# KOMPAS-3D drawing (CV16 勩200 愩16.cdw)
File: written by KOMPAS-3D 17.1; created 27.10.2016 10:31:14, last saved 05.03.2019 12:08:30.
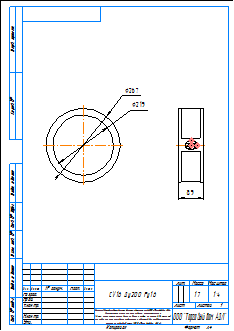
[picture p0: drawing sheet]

Sheet 1: A4, portrait

Title block, sheet 1: name: CV16 Ду200 Ру16; material: Сталь 20  ГОСТ 1050-88; mass: 17; sheets: 1; sheet format: A4; stored path: \\adlc.lan\data\АДЛ_ПКД\3D-модели\ADL production\Клапаны обратные ГРАНЛОК\CV16\KOMPAS 2D\CV16 Ду200 Ру16.cdw

Views: Вид 1, Проекционный вид 2
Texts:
  Klimkovich
  ADL
  Рама для чертежей
  Лит-Масса-Масштаб
  Материал-Предприятие
  Масштаб
  Изм.
  Лист
  № докум.
  Подп.
  Дата
  Лит.
  Разраб.
  Пров.
  Т.контр.
  Листов
  Внимание! Данный продукт является объектом авторского права ООО «Торговый Дом АДЛ».
  Запрещается изменение, копирование, распространение
  (в том числе путем копирования на другие сайты и ресурсы в Интернете)
  или любое иное использование информации и объектов без предварительного
  согласия правообладателя (ООО «Торговый Дом АДЛ»).
  Н.контр.
  Утв.
  ООО "Торговый дом АДЛ"
  Изменение
  Номер документа
  Подпись
  Обозначение документа
  Наименование изделия
  Масса изделия по ГОСТ 2.109-73
  Порядковый номер листа
  Общее количество листов в документе
  Характер работы, выполненной лицом, подписавшим документ
  Наименование или индекс предприятия, выпускающего документ
  Инв. № подл.
  Подп. и дата
  Взам. инв. №
  Инв. № дубл.
  Инвентарный номер подлинника по ГОСТ 2.501-68
  Подпись принявшего подлинник в отдел технической документации
  Инвентарный номер подлинника, взамен которого выпущен данный подлинник
  Инвентарный номер дубликата по ГОСТ 2.502-68
  Подпись принявшего дубликат в отдел технической документации
  Справ. №
  Перв. примен.
  Обозначение документа, взамен или на основании которого выпущен данный документ
  Обозначение документа, в котором впервые записан данный документ
  Подпись лица, копировавшего чертеж
  Обозначение формата листа
  !Рама для чертежа
Dimensions and other numbers on the sheet: 267; 219; 89; 1:4; 1; 17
